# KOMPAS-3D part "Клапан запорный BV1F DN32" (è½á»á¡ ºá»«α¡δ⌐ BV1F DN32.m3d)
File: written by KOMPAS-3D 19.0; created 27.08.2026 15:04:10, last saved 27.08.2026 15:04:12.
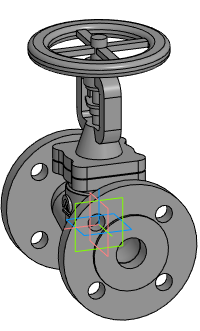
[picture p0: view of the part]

Document properties: Автор: Энергия; Полное имя файла: E:\Dendor\_3D для проектировщиков\5.6 Клапан запорный BV1F\stp\Клапан запорный BV1F DN32.m3d

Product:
- Part/product: Клапан запорный BV1F DN32
    Масса: 8.34122

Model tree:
1. Операция без истории:1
